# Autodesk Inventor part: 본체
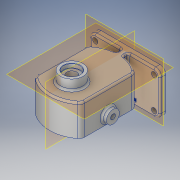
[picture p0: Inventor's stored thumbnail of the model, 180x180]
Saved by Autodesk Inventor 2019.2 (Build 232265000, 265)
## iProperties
Created: 2019-03
Part Number: 본체
Material: 알루미늄 6061
Document SubType Name: Modeling
Designer: User
Density: 2.7 g/cm^3
Appearance: 알루미늄 - 평지
Mass: 1187.2 g
Surface Area: 719.418 cm^2
Volume: 439.702 cm^3
Author: User
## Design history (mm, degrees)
sketch "스케치1"
  geometry: L1 (-84, 0)-(84, 0) reference; L2 (0, 14.6)-(0, -87.6) reference; L3 (-60, -73)-(60, -73); L4 (60, -73)-(60, 0); L5 (60, 0)-(-60, 0); L6 (-60, 0)-(-60, -73); L7 (-60, -73)-(60, 0); L8 (60, -73)-(-60, 0); 2 further points
  constraints: 12 end point, 3 midpoint, 2 parallel, 1 horizontal, 1 perpendicular, 1 point on line
  dimensions: "d0" = 73 distance of L3.end L4.end; "d1" = 120 distance of L3.start L3.end
extrude "돌출1" new body sketch "스케치1" distance "d2" = 10; taper "d3" = 0 deg
sketch "스케치3"
  geometry: L1 (0, 0)-(-43, 0); L2 (-43, 0)-(-43, 90.686); L3 (-43, 90.686)-(0, 90.686); L4 (0, 90.686)-(0, 0)
  constraints: 8 end point, 2 parallel, 1 horizontal, 1 perpendicular
  dimensions: "d6" = 43 distance of L1.start L1.end; "d7" = 90.68632 distance between parallel lines of L1 L3
extrude "돌출2" join sketch "스케치3" stored distance "d8" = 12; taper "d9" = 0 deg
sketch "스케치4"
  geometry: L1 (-40, 112.721)-(-40, 23.279); L2 (40, 112.721)-(40, 23.279); L3 (-200.879, 0)-(139.916, 0) reference; L4 (0, -37.6)-(0, 155.6) reference; L5 (0, 128)-(-50.417, 128); L6 (40, 112.721)-(-40, 112.721); L7 (40, 23.279)-(-40, 23.279); L8 (-60, -10)-(60, -10) reference; A1 r 60 centre (0, 68) between (40, 112.721) and (-40, 112.721); A2 r 60 centre (0, 68) between (-40, 23.279) and (40, 23.279); 1 further point
  constraints: 10 end point, 5 point on circle, 2 centre point, 2 horizontal, 2 perpendicular, 1 parallel, 1 point on line, 1 tangent, 1 other
  dimensions: "d23" = 80 distance between parallel lines of L2 L1; "d25" = 60 radius of A1; "d26" = 60 radius of A2; "d29" = 138 distance between parallel lines of L8 L5
extrude "돌출3" join sketch "스케치4" distance "d14" = 53; taper "d15" = 0 deg
sketch "스케치5"
  geometry: L1 (24, 90)-(24, 46); L2 (-24, 90)-(-24, 46); L3 (0, 155.6)-(0, -37.6) reference; L4 (-78.912, 68)-(103.855, 68); L5 (60, -10)-(-60, -10) reference; A1 r 24 centre (0, 90) between (24, 90) and (-24, 90); A2 r 24 centre (0, 46) between (-24, 46) and (24, 46); 1 further point
  constraints: 6 end point, 4 point on circle, 4 tangent, 2 centre point, 2 point on line, 1 horizontal, 1 parallel
  dimensions: "d21" = 44 distance of A2.centre A1.centre; "d22" = 24 radius of A1; "d27" = 22 distance from line of L1.end L4; "d28" = 78 distance between parallel lines of L5 L4
extrude "돌출4" cut sketch "스케치5" distance "d30" = 29; taper "d31" = 0 deg
sketch "스케치6"
  geometry: A1 r 24 centre (0, 90) between (24, 90) and (-24, 90) reference; 2 further points
  constraints: 1 coincident
hole "구멍1" sketch "스케치6" at (0, 90) diameter "d32" = 25; stored, may be unused: countersink angle "d36" = 82 deg, drill point angle "d38" = 0 deg; dims "d33" = 12, "d34" = 3.023, "d35" = 2, "d37" = 15
sketch "스케치7"
  geometry: A1 r 24 centre (0, 46) between (-24, 46) and (24, 46) reference; 2 further points
  constraints: 1 coincident
hole "구멍2" sketch "스케치7" at (0, 46) diameter "d39" = 25; stored, may be unused: countersink angle "d43" = 82 deg, drill point angle "d45" = 0 deg; dims "d40" = 12, "d41" = 3.023, "d42" = 2, "d44" = 15
sketch "스케치9"
  geometry: C1 r 19 at (60, -100); C2 r 12.5 at (60, -100) reference; 1 further point
  constraints: 1 centre point, 1 concentric
  dimensions: "d47" = 38 diameter of C1
extrude "돌출5" join sketch "스케치9" distance "d48" = 17; taper "d49" = 0 deg
sketch "스케치10"
  geometry: C1 r 19 at (0, 0) reference; 2 further points
  constraints: 1 coincident
hole "구멍3" sketch "스케치10" at (0, 0) diameter "d50" = 17; stored, may be unused: countersink angle "d54" = 82 deg, drill point angle "d56" = 0 deg; dims "d51" = 12, "d52" = 28, "d53" = 7.3, "d55" = 15
sketch "스케치11"
  geometry: L1 (-24, 46)-(-24, 90) reference; L2 (24, 90)-(24, 46) reference; L3 (0, 90)-(0, 121); A1 r 24 centre (0, 90) between (24, 90) and (-24, 90) reference; A2 r 24 centre (0, 46) between (-24, 46) and (24, 46) reference; 1 further point
  constraints: 2 end point, 1 vertical
  dimensions: "d57" = 31 distance of L3.start L3.end
hole "구멍4" sketch "스케치11" at (0, 121) diameter "d58" = 4.134; stored, may be unused: countersink angle "d62" = 82 deg, drill point angle "d64" = 118 deg; dims "d59" = 10, "d60" = 3.023, "d61" = 7.3, "d63" = 12
sketch "스케치12"
  geometry: L1 (24, 90)-(24, 46) reference; L2 (-24, 46)-(-24, 90) reference; L3 (0, 90)-(-31, 90); L4 (-31, 90)-(-31, 46); A1 r 24 centre (0, 90) between (24, 90) and (-24, 90) reference; A2 r 24 centre (0, 46) between (-24, 46) and (24, 46) reference; 1 further point
  constraints: 4 end point, 1 horizontal, 1 perpendicular
  dimensions: "d65" = 44 distance of L3.end L4.end; "d66" = 31 distance of L3.start L3.end
hole "구멍5" sketch "스케치12" at (-31, 90), (-31, 46) diameter "d67" = 4.134; stored, may be unused: countersink angle "d71" = 82 deg, drill point angle "d73" = 118 deg; dims "d68" = 10, "d69" = 3.023, "d70" = 7.3, "d72" = 12
sketch "스케치14"
  geometry: L1 (104.721, 0)-(104.721, -53) reference; L2 (44.721, 58.042)-(44.721, -160.194); L3 (-23.279, -73)-(-33.279, -73) reference; L4 (89.443, -53)-(0, -53) reference; C1 r 11 at (44.721, -39); 1 further point
  constraints: 2 end point, 1 centre point, 1 point on line, 1 vertical
  dimensions: "d77" = 22 diameter of C1; "d78" = 60 distance between parallel lines of L2 L1; "d117" = 14 distance from line of C1.centre L4
extrude "돌출6" join sketch "스케치14" distance "d80" = 8; taper "d81" = 0 deg
sketch "스케치15"
  geometry: C1 r 11 at (0, 0) reference; 2 further points
  constraints: 1 coincident
hole "구멍6" sketch "스케치15" at (0, 0) diameter "d82" = 8.376; stored, may be unused: countersink angle "d86" = 82 deg, drill point angle "d88" = 118 deg; dims "d83" = 40, "d84" = 3.023, "d85" = 7.3, "d87" = 27.3
fillet "모깎기1" dims "d89" = 10
fillet "모깎기2" dims "d90" = 3
fillet "모깎기3" dims "d91" = 3
fillet "모깎기4" dims "d92" = 3
fillet "모깎기5" dims "d93" = 10
fillet "모깎기6" dims "d94" = 3
fillet "모깎기7" dims "d95" = 3
fillet "모깎기8" dims "d96" = 0.5
chamfer "모따기2" distance "d100" = 1; stored, may be unused: second distance "d101" = 2, angle "d102" = 30 deg
sketch "스케치16"
  geometry: L1 (-50, -73)-(50, -73) reference; L2 (-60, -10)-(-60, -63) reference; 2 further points
  constraints: 1 other
  dimensions: "d103" = 10 distance from line of L1 point (0, -63); "d104" = 60 distance from line of point (0, -63) L2
feature "엠보싱1" sketch "스케치16" dims "d23" = 80, "d25" = 60, "d26" = 60, "d29" = 138, "d105" = 0.5, "d106" = 0
sketch "스케치17"
  geometry: C1 r 4.5 at (-50, -10); C2 r 4.5 at (-50, -63); A1 r 10 centre (-50, -10) between (-50, 0) and (-60, -10) reference; A2 r 10 centre (-50, -63) between (-60, -63) and (-50, -73) reference; 1 further point
  constraints: 2 centre point, 2 concentric
  dimensions: "d107" = 9 diameter of C1; "d108" = 9 diameter of C2
extrude "돌출7" cut sketch "스케치17" distance "d109" = 10; taper "d110" = 0 deg
chamfer "모따기3" distance "d111" = 1; stored, may be unused: second distance "d112" = 2, angle "d113" = 45 deg
chamfer "모따기4" distance "d114" = 0.7; stored, may be unused: second distance "d115" = 2, angle "d116" = 30 deg
node "솔리드1"
mirror "미러1"
pattern_linear "직사각형 패턴1" dims "d76" = 106
mirror "미러2"
mirror "미러3"
other parameters: "d24" = 83.65028
